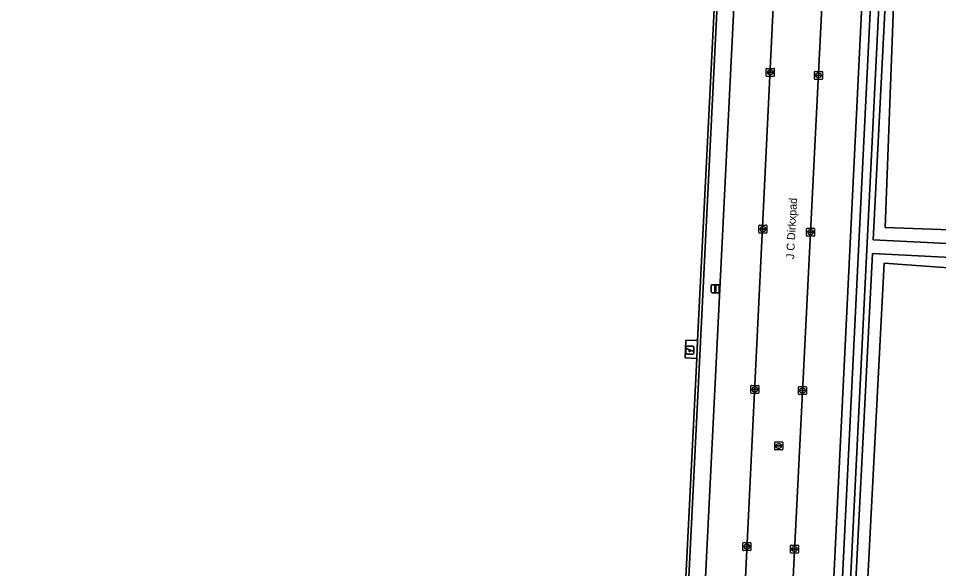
# Model space of a CAD drawing. Extents: x 161758 to 162722, y 384793 to 385405.
# Drawn here: x 162311.3 to 162426.3, y 385251.9 to 385320.8 of the extents above; entities that cross this region are included whole.
import ezdxf

# ---------------------------------------------------------------- set-up
doc = ezdxf.new("R2010")
doc.units = 0
for name, color, linetype in [('IMGEO_Grasland_overig', 7, 'Continuous'), ('IMGEO_Groenvoorziening', 7, 'Continuous'), ('IMGEO_Kolk', 7, 'Continuous'), ('IMGEO_Lichtmast', 7, 'Continuous'), ('IMGEO_Loofbos', 7, 'Continuous'), ('IMGEO_Oever', 7, 'Continuous'), ('IMGEO_Openbare_ruimte_label', 7, 'Continuous'), ('IMGEO_Parkeervlak_open', 7, 'Continuous'), ('IMGEO_Rijbaan_lokaal_open', 7, 'Continuous'), ('IMGEO_Rioolput', 7, 'Continuous'), ('IMGEO_Speelvoorziening', 7, 'Continuous'), ('IMGEO_Voetpad_open', 7, 'Continuous'), ('IMGEO_Waterloop', 7, 'Continuous')]:
    doc.layers.add(name, color=color, linetype=linetype)

msp = doc.modelspace()

# ---------------------------------------------------------------- linework, layer by layer
at = {"layer": 'IMGEO_Grasland_overig'}
msp.add_lwpolyline([(162432.84, 385355.41), (162421.91, 385355.65), (162419.64, 385294.6), (162436.99, 385293.98)], dxfattribs=at)
at = {"layer": 'IMGEO_Groenvoorziening'}
for points in [[(162406.77, 385119.45), (162407.78, 385119.36), (162414.26, 385250), (162419.4, 385355.71), (162418.35, 385355.76), (162413.18, 385250), (162407.03, 385124.71)], [(162394.71, 385280.53), (162396.19, 385280.46), (162399.11, 385339.34), (162399.18, 385340.91), (162397, 385340.93), (162396.99, 385342.55), (162298.97, 385341.5), (162296.52, 385340.72), (162294.55, 385339.26), (162293.2, 385337.18), (162292.28, 385334.73), (162292.13, 385333.4), (162291.99, 385332.12), (162286, 385220.39), (162392.94, 385214.82), (162394.68, 385250), (162396.08, 385278.24), (162394.61, 385278.31)]]:
    msp.add_lwpolyline(points, close=True, dxfattribs=at)
at = {"layer": 'IMGEO_Kolk'}
for p, q in [((162404.77, 385313.6), (162404.77, 385314.45)), ((162404.85, 385314.52), (162405.7, 385314.52)), ((162405.7, 385313.52), (162404.85, 385313.52)), ((162405.03, 385314.02), (162405.03, 385314.03)), ((162405.07, 385314.07), (162405.47, 385314.07)), ((162405.47, 385313.98), (162405.07, 385313.98)), ((162405.26, 385314.3), (162405.29, 385314.3)), ((162405.28, 385313.74), (162405.26, 385313.74)), ((162405.52, 385314.03), (162405.52, 385314.02)), ((162405.77, 385314.45), (162405.77, 385313.6)), ((162410.78, 385313.22), (162410.78, 385314.08)), ((162410.85, 385314.15), (162411.7, 385314.15)), ((162411.03, 385313.64), (162411.03, 385313.66)), ((162411.47, 385313.61), (162411.07, 385313.61)), ((162411.08, 385313.69), (162411.47, 385313.69)), ((162411.26, 385313.93), (162411.29, 385313.93)), ((162411.52, 385313.66), (162411.52, 385313.64)), ((162411.78, 385314.08), (162411.78, 385313.22)), ((162411.7, 385313.15), (162410.85, 385313.15)), ((162411.29, 385313.37), (162411.26, 385313.37)), ((162403.85, 385293.99), (162403.85, 385294.84)), ((162403.92, 385294.91), (162404.77, 385294.91)), ((162404.11, 385294.41), (162404.11, 385294.42)), ((162404.15, 385294.46), (162404.55, 385294.46)), ((162404.54, 385294.37), (162404.15, 385294.37)), ((162404.36, 385294.13), (162404.33, 385294.13)), ((162404.34, 385294.69), (162404.36, 385294.69)), ((162404.59, 385294.42), (162404.59, 385294.41)), ((162404.85, 385294.84), (162404.85, 385293.99)), ((162409.8, 385293.6), (162409.8, 385294.46)), ((162409.87, 385294.53), (162410.73, 385294.53)), ((162410.06, 385294.02), (162410.06, 385294.04)), ((162410.1, 385294.07), (162410.5, 385294.07)), ((162410.5, 385293.99), (162410.1, 385293.99)), ((162410.29, 385294.31), (162410.31, 385294.31)), ((162410.54, 385294.04), (162410.54, 385294.02)), ((162410.8, 385294.46), (162410.8, 385293.6)), ((162404.77, 385293.91), (162403.92, 385293.91)), ((162410.73, 385293.53), (162409.87, 385293.53)), ((162410.31, 385293.75), (162410.28, 385293.75)), ((162402.84, 385273.94), (162402.84, 385274.79)), ((162402.91, 385274.86), (162403.77, 385274.86)), ((162403.14, 385274.41), (162403.54, 385274.41)), ((162403.33, 385274.64), (162403.35, 385274.64)), ((162403.84, 385274.79), (162403.84, 385273.94)), ((162408.79, 385273.8), (162408.79, 385274.65)), ((162408.86, 385274.72), (162409.72, 385274.72)), ((162409.28, 385274.5), (162409.3, 385274.5)), ((162409.79, 385274.65), (162409.79, 385273.8)), ((162403.77, 385273.86), (162402.91, 385273.86)), ((162403.1, 385274.36), (162403.1, 385274.37)), ((162403.54, 385274.32), (162403.14, 385274.32)), ((162403.35, 385274.08), (162403.32, 385274.08)), ((162403.58, 385274.37), (162403.58, 385274.36)), ((162409.72, 385273.72), (162408.86, 385273.72)), ((162409.05, 385274.22), (162409.05, 385274.23)), ((162409.09, 385274.27), (162409.49, 385274.27)), ((162409.49, 385274.18), (162409.09, 385274.18)), ((162409.3, 385273.94), (162409.28, 385273.94)), ((162409.53, 385274.23), (162409.53, 385274.22)), ((162401.85, 385254.27), (162401.85, 385255.12)), ((162401.93, 385255.2), (162402.78, 385255.2)), ((162402.34, 385254.98), (162402.37, 385254.98)), ((162402.85, 385255.12), (162402.85, 385254.27)), ((162407.86, 385254.89), (162408.72, 385254.89)), ((162402.78, 385254.2), (162401.93, 385254.2)), ((162402.11, 385254.69), (162402.11, 385254.7)), ((162402.55, 385254.65), (162402.15, 385254.65)), ((162402.16, 385254.74), (162402.55, 385254.74)), ((162402.36, 385254.42), (162402.34, 385254.42)), ((162402.6, 385254.7), (162402.6, 385254.69)), ((162407.79, 385253.96), (162407.79, 385254.82)), ((162408.72, 385253.89), (162407.86, 385253.89)), ((162408.05, 385254.38), (162408.05, 385254.4)), ((162408.09, 385254.43), (162408.49, 385254.43)), ((162408.49, 385254.35), (162408.09, 385254.35)), ((162408.3, 385254.11), (162408.27, 385254.11)), ((162408.28, 385254.67), (162408.3, 385254.67)), ((162408.53, 385254.4), (162408.53, 385254.38)), ((162408.79, 385254.82), (162408.79, 385253.96))]:
    msp.add_line(p, q, dxfattribs=at)
for points in [[(162404.77, 385313.6), (162404.77, 385314.45)], [(162404.85, 385314.52), (162405.7, 385314.52)], [(162405.7, 385313.52), (162404.85, 385313.52)], [(162405.77, 385314.45), (162405.77, 385313.6)], [(162410.78, 385313.22), (162410.78, 385314.08)], [(162410.85, 385314.15), (162411.7, 385314.15)], [(162411.78, 385314.08), (162411.78, 385313.22)], [(162411.7, 385313.15), (162410.85, 385313.15)], [(162403.85, 385293.99), (162403.85, 385294.84)], [(162403.92, 385294.91), (162404.77, 385294.91)], [(162404.85, 385294.84), (162404.85, 385293.99)], [(162409.8, 385293.6), (162409.8, 385294.46)], [(162409.87, 385294.53), (162410.73, 385294.53)], [(162410.8, 385294.46), (162410.8, 385293.6)], [(162404.77, 385293.91), (162403.92, 385293.91)], [(162410.73, 385293.53), (162409.87, 385293.53)], [(162402.84, 385273.94), (162402.84, 385274.79)], [(162402.91, 385274.86), (162403.77, 385274.86)], [(162403.84, 385274.79), (162403.84, 385273.94)], [(162408.79, 385273.8), (162408.79, 385274.65)], [(162408.86, 385274.72), (162409.72, 385274.72)], [(162409.79, 385274.65), (162409.79, 385273.8)], [(162403.77, 385273.86), (162402.91, 385273.86)], [(162409.72, 385273.72), (162408.86, 385273.72)], [(162401.85, 385254.27), (162401.85, 385255.12)], [(162401.93, 385255.2), (162402.78, 385255.2)], [(162402.85, 385255.12), (162402.85, 385254.27)], [(162407.86, 385254.89), (162408.72, 385254.89)], [(162402.78, 385254.2), (162401.93, 385254.2)], [(162407.79, 385253.96), (162407.79, 385254.82)], [(162408.72, 385253.89), (162407.86, 385253.89)], [(162408.79, 385254.82), (162408.79, 385253.96)]]:
    msp.add_lwpolyline(points, dxfattribs=at)
for centre, radius, start, end in [((162404.85, 385314.45), 0.0765, 91.552, 178.448), ((162404.85, 385314.45), 0.0765, 91.552, 178.448), ((162404.85, 385313.6), 0.0765, 181.552, 268.448), ((162404.85, 385313.6), 0.0765, 181.552, 268.448), ((162405.07, 385314.03), 0.0403, 85.8775, 175.7526), ((162405.07, 385314.02), 0.0366, 178.938, 274.7102), ((162405.48, 385314.03), 0.0386, 1.7309, 96.639), ((162405.47, 385314.02), 0.043, 264.8664, 352.4533), ((162405.7, 385314.45), 0.0765, 1.552, 88.448), ((162405.7, 385314.45), 0.0765, 1.552, 88.448), ((162405.7, 385313.6), 0.0765, 271.552, 358.448), ((162405.7, 385313.6), 0.0765, 271.552, 358.448), ((162410.85, 385314.07), 0.0765, 91.552, 178.448), ((162410.85, 385314.07), 0.0765, 91.552, 178.448), ((162411.07, 385313.65), 0.0403, 85.8775, 175.7526), ((162411.07, 385313.64), 0.0366, 178.938, 274.7102), ((162411.48, 385313.65), 0.0386, 1.7309, 96.639), ((162411.48, 385313.65), 0.043, 264.8664, 352.4533), ((162411.7, 385314.07), 0.0765, 1.552, 88.448), ((162411.7, 385314.07), 0.0765, 1.552, 88.448), ((162410.85, 385313.22), 0.0765, 181.552, 268.448), ((162410.85, 385313.22), 0.0765, 181.552, 268.448), ((162411.7, 385313.22), 0.0765, 271.552, 358.448), ((162411.7, 385313.22), 0.0765, 271.552, 358.448), ((162403.92, 385294.84), 0.0765, 91.552, 178.448), ((162403.92, 385294.84), 0.0765, 91.552, 178.448), ((162403.92, 385293.99), 0.0765, 181.552, 268.448), ((162403.92, 385293.99), 0.0765, 181.552, 268.448), ((162404.15, 385294.42), 0.0403, 85.8775, 175.7526), ((162404.14, 385294.41), 0.0366, 178.938, 274.7102), ((162404.55, 385294.41), 0.043, 264.8664, 352.4533), ((162404.55, 385294.42), 0.0386, 1.7309, 96.639), ((162404.77, 385294.84), 0.0765, 1.552, 88.448), ((162404.77, 385294.84), 0.0765, 1.552, 88.448), ((162404.77, 385293.99), 0.0765, 271.552, 358.448), ((162404.77, 385293.99), 0.0765, 271.552, 358.448), ((162409.88, 385294.45), 0.0765, 91.552, 178.448), ((162409.88, 385294.45), 0.0765, 91.552, 178.448), ((162410.1, 385294.03), 0.0403, 85.8775, 175.7526), ((162410.09, 385294.02), 0.0366, 178.938, 274.7102), ((162410.5, 385294.03), 0.0386, 1.7309, 96.639), ((162410.5, 385294.03), 0.043, 264.8664, 352.4533), ((162410.72, 385294.45), 0.0765, 1.552, 88.448), ((162410.72, 385294.45), 0.0765, 1.552, 88.448), ((162409.88, 385293.6), 0.0765, 181.552, 268.448), ((162409.88, 385293.6), 0.0765, 181.552, 268.448), ((162410.72, 385293.6), 0.0765, 271.552, 358.448), ((162410.72, 385293.6), 0.0765, 271.552, 358.448), ((162402.92, 385274.79), 0.0765, 91.552, 178.448), ((162402.92, 385274.79), 0.0765, 91.552, 178.448), ((162403.14, 385274.37), 0.0403, 85.8775, 175.7526), ((162403.54, 385274.37), 0.0386, 1.7309, 96.639), ((162403.76, 385274.79), 0.0765, 1.552, 88.448), ((162403.76, 385274.79), 0.0765, 1.552, 88.448), ((162408.87, 385274.65), 0.0765, 91.552, 178.448), ((162408.87, 385274.65), 0.0765, 91.552, 178.448), ((162409.71, 385274.65), 0.0765, 1.552, 88.448), ((162409.71, 385274.65), 0.0765, 1.552, 88.448), ((162402.92, 385273.94), 0.0765, 181.552, 268.448), ((162402.92, 385273.94), 0.0765, 181.552, 268.448), ((162403.13, 385274.36), 0.0366, 178.938, 274.7102), ((162403.54, 385274.36), 0.043, 264.8664, 352.4533), ((162403.76, 385273.94), 0.0765, 271.552, 358.448), ((162403.76, 385273.94), 0.0765, 271.552, 358.448), ((162408.87, 385273.8), 0.0765, 181.552, 268.448), ((162408.87, 385273.8), 0.0765, 181.552, 268.448), ((162409.09, 385274.23), 0.0403, 85.8775, 175.7526), ((162409.09, 385274.22), 0.0366, 178.938, 274.7102), ((162409.49, 385274.23), 0.0386, 1.7309, 96.639), ((162409.49, 385274.22), 0.043, 264.8664, 352.4533), ((162409.71, 385273.8), 0.0765, 271.552, 358.448), ((162409.71, 385273.8), 0.0765, 271.552, 358.448), ((162401.93, 385255.12), 0.0765, 91.552, 178.448), ((162401.93, 385255.12), 0.0765, 91.552, 178.448), ((162402.78, 385255.12), 0.0765, 1.552, 88.448), ((162402.78, 385255.12), 0.0765, 1.552, 88.448), ((162407.87, 385254.81), 0.0765, 91.552, 178.448), ((162407.87, 385254.81), 0.0765, 91.552, 178.448), ((162408.71, 385254.81), 0.0765, 1.552, 88.448), ((162408.71, 385254.81), 0.0765, 1.552, 88.448), ((162401.93, 385254.27), 0.0765, 181.552, 268.448), ((162401.93, 385254.27), 0.0765, 181.552, 268.448), ((162402.15, 385254.7), 0.0403, 85.8775, 175.7526), ((162402.15, 385254.69), 0.0366, 178.938, 274.7102), ((162402.56, 385254.7), 0.0386, 1.7309, 96.639), ((162402.55, 385254.7), 0.043, 264.8664, 352.4533), ((162402.78, 385254.27), 0.0765, 271.552, 358.448), ((162402.78, 385254.27), 0.0765, 271.552, 358.448), ((162407.87, 385253.97), 0.0765, 181.552, 268.448), ((162407.87, 385253.97), 0.0765, 181.552, 268.448), ((162408.09, 385254.39), 0.0403, 85.8775, 175.7526), ((162408.08, 385254.38), 0.0366, 178.938, 274.7102), ((162408.49, 385254.39), 0.0386, 1.7309, 96.639), ((162408.49, 385254.39), 0.043, 264.8664, 352.4533), ((162408.71, 385253.97), 0.0765, 271.552, 358.448), ((162408.71, 385253.97), 0.0765, 271.552, 358.448)]:
    msp.add_arc(centre, radius, start, end, dxfattribs=at)
for centre, major_axis, ratio, start_param, end_param in [((162405.26, 385314.02), (-0.387, 0.002), 0.722429, 4.712389, 7.853982), ((162405.28, 385314.02), (-0.39, 0.002), 0.717154, 1.570796, 4.712389), ((162411.26, 385313.65), (-0.387, 0.002), 0.722429, 4.712389, 7.853982), ((162411.29, 385313.65), (-0.39, 0.002), 0.717154, 1.570796, 4.712389), ((162404.33, 385294.41), (-0.387, 0.002), 0.722429, 4.712389, 7.853982), ((162404.36, 385294.41), (-0.39, 0.002), 0.717154, 1.570796, 4.712389), ((162410.29, 385294.03), (-0.387, 0.002), 0.722429, 4.712389, 7.853982), ((162410.31, 385294.03), (-0.39, 0.002), 0.717154, 1.570796, 4.712389), ((162403.33, 385274.36), (-0.387, 0.002), 0.722429, 4.712389, 7.853982), ((162403.35, 385274.36), (-0.39, 0.002), 0.717154, 1.570796, 4.712389), ((162409.28, 385274.22), (-0.387, 0.002), 0.722429, 4.712389, 7.853982), ((162409.3, 385274.22), (-0.39, 0.002), 0.717154, 1.570796, 4.712389), ((162402.34, 385254.7), (-0.387, 0.002), 0.722429, 4.712389, 7.853982), ((162402.36, 385254.7), (-0.39, 0.002), 0.717154, 1.570796, 4.712389), ((162408.28, 385254.39), (-0.387, 0.002), 0.722429, 4.712389, 7.853982), ((162408.3, 385254.39), (-0.39, 0.002), 0.717154, 1.570796, 4.712389)]:
    msp.add_ellipse(centre, major_axis=major_axis, ratio=ratio, start_param=start_param, end_param=end_param, dxfattribs=at)
at = {"layer": 'IMGEO_Lichtmast'}
for p, q in [((162397.9, 385286.56), (162397.9, 385287.36)), ((162397.9, 385287.36), (162397.9, 385286.56)), ((162398, 385287.46), (162398.79, 385287.46)), ((162398.79, 385287.46), (162398, 385287.46)), ((162398.89, 385287.36), (162398.89, 385286.56)), ((162398.89, 385286.56), (162398.89, 385287.36)), ((162398.79, 385286.46), (162398, 385286.46)), ((162398, 385286.46), (162398.79, 385286.46))]:
    msp.add_line(p, q, dxfattribs=at)
msp.add_lwpolyline([(162398.32, 385287.34), (162398.47, 385287.34), (162398.47, 385286.59), (162398.32, 385286.59), (162398.32, 385287.34)], dxfattribs=at)
for centre, start, end in [((162398, 385287.36), 90, 180), ((162398, 385287.36), 90, 180), ((162398.79, 385287.36), 0, 90), ((162398.79, 385287.36), 360, 90), ((162398, 385286.56), 180, 270), ((162398, 385286.56), 180, 270), ((162398.79, 385286.56), 270, 0), ((162398.79, 385286.56), 270, 0)]:
    msp.add_arc(centre, 0.1, start, end, dxfattribs=at)
at = {"layer": 'IMGEO_Loofbos'}
msp.add_lwpolyline([(162465.14, 385194.9), (162467.71, 385212.41), (162470.01, 385237.54), (162469.87, 385258.53), (162470.68, 385264.61), (162472.24, 385270.69), (162476.28, 385280.29), (162478.41, 385287.09), (162477.2, 385287.09), (162434.99, 385289.01), (162419.49, 385290.14), (162417.4, 385250), (162410.58, 385119.13), (162408.17, 385119.33), (162408.1, 385118.2), (162406.42, 385117.44)], dxfattribs=at)
at = {"layer": 'IMGEO_Oever'}
for points in [[(162419.64, 385294.6), (162421.91, 385355.65), (162421.92, 385356.05), (162419.42, 385356.14), (162419.4, 385355.71), (162414.26, 385250), (162407.78, 385119.36), (162408.17, 385119.33), (162410.58, 385119.13), (162417.4, 385250), (162419.49, 385290.14), (162434.99, 385289.01), (162477.2, 385287.09), (162478.24, 385291.84), (162436.99, 385293.98)], [(162418.13, 385293.08), (162476.31, 385290.2), (162475.89, 385288.42), (162418.05, 385291.37), (162409.41, 385121.97), (162408.95, 385121.99), (162420.33, 385352.73), (162421.17, 385352.69)]]:
    msp.add_lwpolyline(points, close=True, dxfattribs=at)
at = {"layer": 'IMGEO_Parkeervlak_open'}
for points in [[(162400.62, 385220.04), (162402.12, 385250), (162407.37, 385358.3)], [(162413.52, 385357.91), (162408.07, 385250), (162405.72, 385201.84), (162401.86, 385124.21), (162402.11, 385124.72)], [(162405.23, 385356.38), (162402.41, 385356.55), (162397.14, 385250), (162395.76, 385222.3), (162398.54, 385222.07)], [(162402.58, 385125), (162407.03, 385124.71), (162413.18, 385250), (162418.35, 385355.76), (162415.08, 385355.95)]]:
    msp.add_lwpolyline(points, dxfattribs=at)
at = {"layer": 'IMGEO_Rijbaan_lokaal_open'}
msp.add_lwpolyline([(162408.07, 385250), (162413.52, 385357.91), (162413.53, 385358.2), (162407.38, 385358.42), (162407.37, 385358.3), (162402.12, 385250), (162400.62, 385220.04)], dxfattribs=at)
at = {"layer": 'IMGEO_Rioolput'}
for p, q in [((162405.82, 385266.87), (162405.82, 385267.72)), ((162405.89, 385267.79), (162406.74, 385267.79)), ((162406.3, 385267.57), (162406.33, 385267.57)), ((162406.82, 385267.72), (162406.82, 385266.87)), ((162406.74, 385266.79), (162405.89, 385266.79)), ((162406.07, 385267.29), (162406.07, 385267.3)), ((162406.51, 385267.25), (162406.11, 385267.25)), ((162406.12, 385267.34), (162406.52, 385267.34)), ((162406.33, 385267.01), (162406.3, 385267.01)), ((162406.56, 385267.3), (162406.56, 385267.29))]:
    msp.add_line(p, q, dxfattribs=at)
for points in [[(162405.82, 385266.87), (162405.82, 385267.72)], [(162405.89, 385267.79), (162406.74, 385267.79)], [(162406.82, 385267.72), (162406.82, 385266.87)], [(162406.74, 385266.79), (162405.89, 385266.79)]]:
    msp.add_lwpolyline(points, dxfattribs=at)
for centre, radius, start, end in [((162405.89, 385267.72), 0.0765, 91.552, 178.448), ((162405.89, 385267.72), 0.0765, 91.552, 178.448), ((162406.74, 385267.72), 0.0765, 1.552, 88.448), ((162406.74, 385267.72), 0.0765, 1.552, 88.448), ((162405.89, 385266.87), 0.0765, 181.552, 268.448), ((162405.89, 385266.87), 0.0765, 181.552, 268.448), ((162406.12, 385267.3), 0.0403, 85.8775, 175.7526), ((162406.11, 385267.29), 0.0366, 178.938, 274.7102), ((162406.52, 385267.29), 0.043, 264.8664, 352.4533), ((162406.52, 385267.3), 0.0386, 1.7309, 96.639), ((162406.74, 385266.87), 0.0765, 271.552, 358.448), ((162406.74, 385266.87), 0.0765, 271.552, 358.448)]:
    msp.add_arc(centre, radius, start, end, dxfattribs=at)
for centre, major_axis, ratio, start_param, end_param in [((162406.3, 385267.29), (-0.387, 0.002), 0.722429, 4.712389, 7.853982), ((162406.33, 385267.29), (-0.39, 0.002), 0.717154, 1.570796, 4.712389)]:
    msp.add_ellipse(centre, major_axis=major_axis, ratio=ratio, start_param=start_param, end_param=end_param, dxfattribs=at)
at = {"layer": 'IMGEO_Speelvoorziening'}
for p, q in [((162394.73, 385278.89), (162394.73, 385279.68)), ((162394.73, 385279.68), (162394.73, 385278.89)), ((162395.11, 385279.31), (162394.77, 385279.45)), ((162394.8, 385279.51), (162395.68, 385279.16)), ((162394.83, 385279.78), (162395.62, 385279.78)), ((162395.62, 385279.78), (162394.83, 385279.78)), ((162395.65, 385279.1), (162395.31, 385279.23)), ((162395.72, 385279.68), (162395.72, 385278.89)), ((162395.72, 385278.89), (162395.72, 385279.68)), ((162395.62, 385278.79), (162394.83, 385278.79)), ((162394.83, 385278.79), (162395.62, 385278.79))]:
    msp.add_line(p, q, dxfattribs=at)
for centre, radius, start, end in [((162394.83, 385279.68), 0.1, 90, 180), ((162394.83, 385279.68), 0.1, 90, 180), ((162394.79, 385279.48), 0.0327, 68.078, 248.078), ((162395.19, 385279.22), 0.12, 130.9928, 5.1632), ((162395.62, 385279.68), 0.1, 0, 90), ((162395.62, 385279.68), 0.1, 360, 90), ((162395.66, 385279.13), 0.0327, 248.078, 68.078), ((162394.83, 385278.89), 0.1, 180, 270), ((162394.83, 385278.89), 0.1, 180, 270), ((162395.62, 385278.89), 0.1, 270, 0), ((162395.62, 385278.89), 0.1, 270, 0)]:
    msp.add_arc(centre, radius, start, end, dxfattribs=at)
at = {"layer": 'IMGEO_Voetpad_open'}
msp.add_lwpolyline([(162398.54, 385222.07), (162395.76, 385222.3), (162397.14, 385250), (162402.41, 385356.55), (162402.26, 385356.58), (162402.71, 385365.87), (162400.75, 385366.01), (162400.65, 385364.02), (162400.44, 385359.8), (162400.31, 385357.19), (162400.23, 385354.49), (162395.04, 385250), (162393.28, 385214.71), (162394.85, 385214.72)], dxfattribs=at)
for points in [[(162400.23, 385354.49), (162399.86, 385354.49), (162399.55, 385348.19), (162399.18, 385340.91), (162399.11, 385339.34), (162396.19, 385280.46), (162396.08, 385278.24), (162394.68, 385250), (162392.94, 385214.82), (162392.93, 385214.72), (162393.28, 385214.71), (162395.04, 385250)], [(162396.19, 385280.46), (162394.71, 385280.53), (162394.61, 385278.31), (162396.08, 385278.24)]]:
    msp.add_lwpolyline(points, close=True, dxfattribs=at)
at = {"layer": 'IMGEO_Waterloop'}
msp.add_lwpolyline([(162418.13, 385293.08), (162421.17, 385352.69), (162420.33, 385352.73), (162408.95, 385121.99), (162409.41, 385121.97), (162418.05, 385291.37), (162475.89, 385288.42), (162476.31, 385290.2)], close=True, dxfattribs=at)

# ---------------------------------------------------------------- texts
at = {"layer": 'IMGEO_Openbare_ruimte_label'}
msp.add_text('J C Dirkxpad', height=1, rotation=87.1347, dxfattribs=at).set_placement((162408.24, 385290.65))

doc.saveas('drawing.dxf')
